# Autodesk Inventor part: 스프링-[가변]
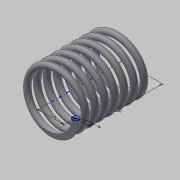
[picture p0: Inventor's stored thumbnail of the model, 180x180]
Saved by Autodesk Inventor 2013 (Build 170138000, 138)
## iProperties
Created: 2015-01
Part Number: 스프링-[가변]
Material: 강철, 탄소
Document SubType Name: Modeling
Designer: Administrator
Density: 7.87 g/cm^3
Mass: 80.13 g
Surface Area: 103.216 cm^2
Volume: 10.1817 cm^3
Author: Administrator
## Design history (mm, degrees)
sketch "스케치1"
  geometry: L1 (0, 0)-(17.5, 0); L2 (17.5, 0)-(17.5, 48.5); L3 (17.5, 48.5)-(0, 48.5); L4 (0, 48.5)-(0, 0); C1 r 2 at (17.5, 0)
  constraints: 8 end point, 2 parallel, 1 centre point, 1 coincident, 1 horizontal, 1 perpendicular
  dimensions: "d0" = 17.5 distance of L1.start L1.end; "d1" = 48.5 distance of L1.end L2.end (derived); "d2" = 4 diameter of C1
feature "코일1" sketch "스케치1" pitch "d3" = 10; turns "d5" = 7.5; dims "d4" = 48.5 (= d1), "d6" = 0, angle "d7" = 90 deg, angle "d8" = 90 deg, "d9" = 0, "d10" = 0
node "작업 평면1"
sketch "스케치2"
  geometry: L1 (-19.5, 0)-(-15.5, 0) reference; L2 (-19.5, 0)-(-15.5, 0) reference; 1 further point
  constraints: 2 horizontal alignment
extrude "돌출1" cut sketch "스케치2" distance "d12" = 10; taper "d13" = 0 deg
node "작업 평면2"
sketch "스케치3"
  geometry: L1 (15.5, 0)-(19.5, 0) reference; 1 further point
  constraints: 1 horizontal alignment
extrude "돌출2" cut sketch "스케치3" distance "d15" = 10; taper "d16" = 0 deg
node "솔리드1"
node "절단 모서리 투영1"
node "절단 모서리 투영2"
node "절단 모서리 투영3"
other parameters: "d11" = 0, "d14" = 48.5 (= d1)
